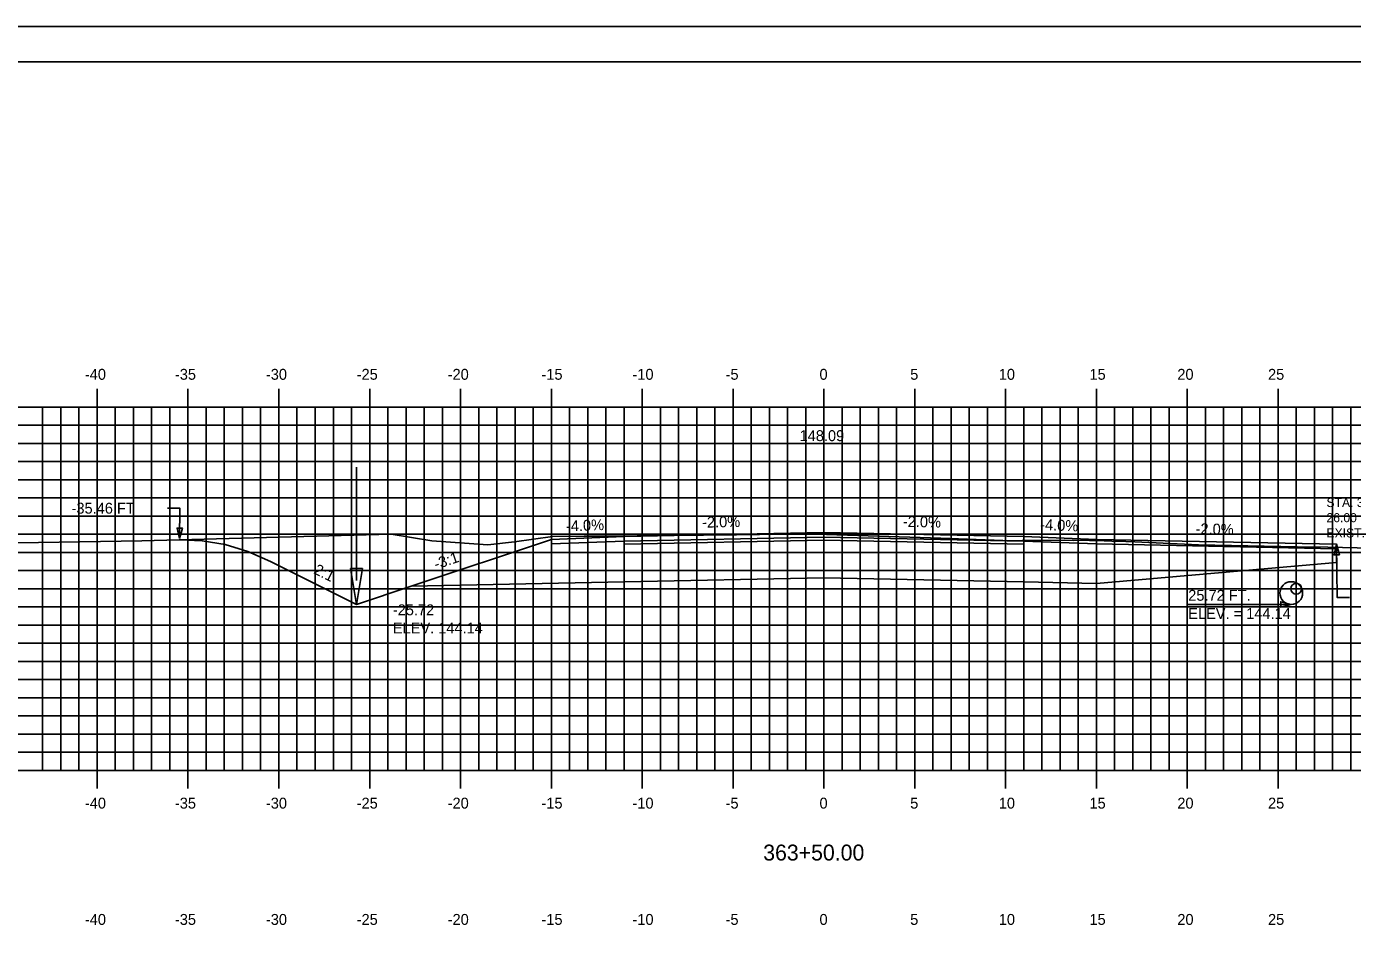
# Model space of a CAD drawing. Extents: x 1146968 to 1147138, y 608981 to 609091.
# Drawn here: x 1147007.3 to 1147080.3, y 609041.6 to 609091.3 of the extents above; entities that cross this region are included whole.
import ezdxf

# ---------------------------------------------------------------- set-up
doc = ezdxf.new("R2010")
doc.units = 0
for name, color, linetype in [('ANNOTATION', 7, 'Continuous'), ('BORDER', 7, 'Continuous'), ('D_Drainage_Culvert', 7, 'Continuous'), ('D_Drainage_Ditch_Line', 7, 'Continuous'), ('D_Roadway_Centerline', 7, 'Continuous'), ('D_Roadway_Centerline_Text', 7, 'Continuous'), ('D_Roadway_Edge_Shoulder', 7, 'Continuous'), ('D_Roadway_Edge_TW', 7, 'Continuous'), ('D_Roadway_Pavement', 7, 'Continuous'), ('D_Roadway_SlopeLines', 7, 'Continuous'), ('D_Roadway_SubGrade', 7, 'Continuous'), ('D_Text_Monospaced', 7, 'Continuous'), ('D_Text_Standard', 7, 'Continuous'), ('H_V ANNOTATION', 7, 'Continuous'), ('MAJOR', 7, 'Continuous'), ('MINOR', 7, 'Continuous'), ('PLOT BOUNDARY', 7, 'Continuous'), ('S_Drainage_Invert', 7, 'Continuous'), ('S_Roadway_Centerline', 7, 'Continuous')]:
    doc.layers.add(name, color=color, linetype=linetype)

msp = doc.modelspace()

# ---------------------------------------------------------------- linework, layer by layer
msp.add_lwpolyline([(1147015.722, 609063.022), (1147016.972, 609062.975), (1147018.222, 609062.762), (1147019.472, 609062.384), (1147020.722, 609061.842), (1147025.46, 609059.473), (1147028.46, 609060.473), (1147036.183, 609063.047), (1147036.184, 609063.047), (1147040.184, 609063.207), (1147051.184, 609063.427), (1147062.184, 609063.207), (1147066.184, 609063.047), (1147079.407, 609062.783)])
at = {"layer": 'BORDER'}
msp.add_lwpolyline([(1146976.185, 608984.335), (1147136.185, 608984.335), (1147136.185, 609089.335), (1146976.185, 609089.335)], close=True, dxfattribs=at)
at = {"layer": 'D_Drainage_Culvert'}
msp.add_circle((1147076.908, 609060.098), 0.625, dxfattribs=at)
at = {"layer": 'D_Drainage_Ditch_Line'}
msp.add_line((1147025.46, 609060.785), (1147025.46, 609067.028), dxfattribs=at)
msp.add_lwpolyline([(1147025.132, 609061.441), (1147025.788, 609061.441), (1147025.46, 609059.473)], close=True, dxfattribs=at)
at = {"layer": 'D_Roadway_Edge_Shoulder'}
for points in [[(1147040.184, 609063.207), (1147036.184, 609063.047), (1147036.184, 609062.797), (1147040.184, 609062.957)], [(1147062.184, 609063.207), (1147066.184, 609063.047), (1147066.184, 609062.797), (1147062.184, 609062.957)], [(1147066.184, 609063.047), (1147079.407, 609062.783), (1147079.407, 609062.533), (1147066.184, 609062.797)]]:
    msp.add_lwpolyline(points, close=True, dxfattribs=at)
at = {"layer": 'D_Roadway_Edge_TW'}
msp.add_lwpolyline([(1147040.184, 609062.957), (1147040.184, 609063.207), (1147051.184, 609063.427), (1147062.184, 609063.207), (1147062.184, 609062.957), (1147051.184, 609063.177)], close=True, dxfattribs=at)
at = {"layer": 'D_Roadway_Pavement'}
msp.add_lwpolyline([(1147040.184, 609062.79), (1147040.184, 609062.957), (1147051.184, 609063.177), (1147062.184, 609062.957), (1147062.184, 609062.79), (1147051.184, 609063.01)], close=True, dxfattribs=at)
at = {"layer": 'D_Roadway_SlopeLines'}
for points in [[(1147025.46, 609059.473), (1147020.722, 609061.842), (1147019.472, 609062.384), (1147018.222, 609062.762), (1147016.972, 609062.975), (1147015.722, 609063.022)], [(1147028.46, 609060.473), (1147025.46, 609059.473)]]:
    msp.add_lwpolyline(points, dxfattribs=at)
at = {"layer": 'D_Roadway_SubGrade'}
for points in [[(1147040.184, 609062.79), (1147040.184, 609062.957), (1147036.184, 609062.797), (1147036.184, 609063.047), (1147036.183, 609063.047), (1147028.46, 609060.473), (1147040.184, 609060.707)], [(1147040.184, 609060.707), (1147040.184, 609062.79), (1147051.184, 609063.01), (1147062.184, 609062.79), (1147062.184, 609060.707), (1147051.184, 609060.927)], [(1147079.407, 609061.783), (1147079.407, 609062.783), (1147066.184, 609063.047), (1147066.184, 609062.797), (1147062.184, 609062.957), (1147062.184, 609062.79), (1147062.184, 609060.707), (1147066.184, 609060.627)]]:
    msp.add_lwpolyline(points, close=True, dxfattribs=at)
at = {"layer": 'D_Text_Standard'}
msp.add_line((1147071.239, 609059.473), (1147075.675, 609059.473), dxfattribs=at)
for points in [[(1147015.722, 609063.092), (1147015.74, 609064.766), (1147015.06, 609064.766)], [(1147079.407, 609062.783), (1147079.435, 609059.861), (1147080.115, 609059.861)], [(1147076.908, 609059.473), (1147076.355, 609059.473), (1147075.675, 609059.473)]]:
    msp.add_lwpolyline(points, dxfattribs=at)
for points in [[(1147015.722, 609063.092), (1147015.582, 609063.675), (1147015.873, 609063.672)], [(1147079.407, 609062.783), (1147079.558, 609062.202), (1147079.267, 609062.199)], [(1147076.908, 609059.473), (1147076.326, 609059.327), (1147076.326, 609059.618)]]:
    msp.add_lwpolyline(points, close=True, dxfattribs=at)
at = {"layer": 'MAJOR'}
for p, q in [((1147011.184, 609071.337), (1147011.184, 609070.335)), ((1147016.184, 609071.337), (1147016.184, 609070.335)), ((1147021.184, 609071.337), (1147021.184, 609070.335)), ((1147026.184, 609071.337), (1147026.184, 609070.335)), ((1147031.184, 609071.337), (1147031.184, 609070.335)), ((1147036.184, 609071.337), (1147036.184, 609070.335)), ((1147041.184, 609071.337), (1147041.184, 609070.335)), ((1147046.184, 609071.337), (1147046.184, 609070.335)), ((1147051.184, 609071.337), (1147051.184, 609070.335)), ((1147056.184, 609071.337), (1147056.184, 609070.335)), ((1147061.184, 609071.337), (1147061.184, 609070.335)), ((1147066.184, 609071.337), (1147066.184, 609070.335)), ((1147071.184, 609071.337), (1147071.184, 609070.335)), ((1147076.184, 609071.337), (1147076.184, 609070.335)), ((1146981.184, 609070.335), (1147121.184, 609070.335)), ((1146981.184, 609070.335), (1147121.184, 609070.335)), ((1147011.184, 609050.335), (1147011.184, 609070.335)), ((1147016.184, 609050.335), (1147016.184, 609070.335)), ((1147021.184, 609050.335), (1147021.184, 609070.335)), ((1147026.184, 609050.335), (1147026.184, 609070.335)), ((1147031.184, 609050.335), (1147031.184, 609070.335)), ((1147036.184, 609050.335), (1147036.184, 609070.335)), ((1147041.184, 609050.335), (1147041.184, 609070.335)), ((1147046.184, 609050.335), (1147046.184, 609070.335)), ((1147051.184, 609050.335), (1147051.184, 609070.335)), ((1147056.184, 609050.335), (1147056.184, 609070.335)), ((1147061.184, 609050.335), (1147061.184, 609070.335)), ((1147066.184, 609050.335), (1147066.184, 609070.335)), ((1147071.184, 609050.335), (1147071.184, 609070.335)), ((1147076.184, 609050.335), (1147076.184, 609070.335)), ((1146981.184, 609065.335), (1147121.184, 609065.335)), ((1146981.184, 609060.335), (1147121.184, 609060.335)), ((1146981.184, 609055.335), (1147121.184, 609055.335)), ((1146981.184, 609050.335), (1147121.184, 609050.335)), ((1146981.184, 609050.335), (1147121.184, 609050.335)), ((1147011.184, 609049.333), (1147011.184, 609050.335)), ((1147016.184, 609049.333), (1147016.184, 609050.335)), ((1147021.184, 609049.333), (1147021.184, 609050.335)), ((1147026.184, 609049.333), (1147026.184, 609050.335)), ((1147031.184, 609049.333), (1147031.184, 609050.335)), ((1147036.184, 609049.333), (1147036.184, 609050.335)), ((1147041.184, 609049.333), (1147041.184, 609050.335)), ((1147046.184, 609049.333), (1147046.184, 609050.335)), ((1147051.184, 609049.333), (1147051.184, 609050.335)), ((1147056.184, 609049.333), (1147056.184, 609050.335)), ((1147061.184, 609049.333), (1147061.184, 609050.335)), ((1147066.184, 609049.333), (1147066.184, 609050.335)), ((1147071.184, 609049.333), (1147071.184, 609050.335)), ((1147076.184, 609049.333), (1147076.184, 609050.335))]:
    msp.add_line(p, q, dxfattribs=at)
at = {"layer": 'MINOR'}
for p, q in [((1147008.184, 609050.335), (1147008.184, 609070.335)), ((1147009.184, 609050.335), (1147009.184, 609070.335)), ((1147010.184, 609050.335), (1147010.184, 609070.335)), ((1147012.184, 609050.335), (1147012.184, 609070.335)), ((1147013.184, 609050.335), (1147013.184, 609070.335)), ((1147014.184, 609050.335), (1147014.184, 609070.335)), ((1147015.184, 609050.335), (1147015.184, 609070.335)), ((1147017.184, 609050.335), (1147017.184, 609070.335)), ((1147018.184, 609050.335), (1147018.184, 609070.335)), ((1147019.184, 609050.335), (1147019.184, 609070.335)), ((1147020.184, 609050.335), (1147020.184, 609070.335)), ((1147022.184, 609050.335), (1147022.184, 609070.335)), ((1147023.184, 609050.335), (1147023.184, 609070.335)), ((1147024.184, 609050.335), (1147024.184, 609070.335)), ((1147025.184, 609050.335), (1147025.184, 609070.335)), ((1147027.184, 609050.335), (1147027.184, 609070.335)), ((1147028.184, 609050.335), (1147028.184, 609070.335)), ((1147029.184, 609050.335), (1147029.184, 609070.335)), ((1147030.184, 609050.335), (1147030.184, 609070.335)), ((1147032.184, 609050.335), (1147032.184, 609070.335)), ((1147033.184, 609050.335), (1147033.184, 609070.335)), ((1147034.184, 609050.335), (1147034.184, 609070.335)), ((1147035.184, 609050.335), (1147035.184, 609070.335)), ((1147037.184, 609050.335), (1147037.184, 609070.335)), ((1147038.184, 609050.335), (1147038.184, 609070.335)), ((1147039.184, 609050.335), (1147039.184, 609070.335)), ((1147040.184, 609050.335), (1147040.184, 609070.335)), ((1147042.184, 609050.335), (1147042.184, 609070.335)), ((1147043.184, 609050.335), (1147043.184, 609070.335)), ((1147044.184, 609050.335), (1147044.184, 609070.335)), ((1147045.184, 609050.335), (1147045.184, 609070.335)), ((1147047.184, 609050.335), (1147047.184, 609070.335)), ((1147048.184, 609050.335), (1147048.184, 609070.335)), ((1147049.184, 609050.335), (1147049.184, 609070.335)), ((1147050.184, 609050.335), (1147050.184, 609070.335)), ((1147052.184, 609050.335), (1147052.184, 609070.335)), ((1147053.184, 609050.335), (1147053.184, 609070.335)), ((1147054.184, 609050.335), (1147054.184, 609070.335)), ((1147055.184, 609050.335), (1147055.184, 609070.335)), ((1147057.184, 609050.335), (1147057.184, 609070.335)), ((1147058.184, 609050.335), (1147058.184, 609070.335)), ((1147059.184, 609050.335), (1147059.184, 609070.335)), ((1147060.184, 609050.335), (1147060.184, 609070.335)), ((1147062.184, 609050.335), (1147062.184, 609070.335)), ((1147063.184, 609050.335), (1147063.184, 609070.335)), ((1147064.184, 609050.335), (1147064.184, 609070.335)), ((1147065.184, 609050.335), (1147065.184, 609070.335)), ((1147067.184, 609050.335), (1147067.184, 609070.335)), ((1147068.184, 609050.335), (1147068.184, 609070.335)), ((1147069.184, 609050.335), (1147069.184, 609070.335)), ((1147070.184, 609050.335), (1147070.184, 609070.335)), ((1147072.184, 609050.335), (1147072.184, 609070.335)), ((1147073.184, 609050.335), (1147073.184, 609070.335)), ((1147074.184, 609050.335), (1147074.184, 609070.335)), ((1147075.184, 609050.335), (1147075.184, 609070.335)), ((1147077.184, 609050.335), (1147077.184, 609070.335)), ((1147078.184, 609050.335), (1147078.184, 609070.335)), ((1147079.184, 609050.335), (1147079.184, 609070.335)), ((1147080.184, 609050.335), (1147080.184, 609070.335)), ((1146981.184, 609069.335), (1147121.184, 609069.335)), ((1146981.184, 609068.335), (1147121.184, 609068.335)), ((1146981.184, 609067.335), (1147121.184, 609067.335)), ((1146981.184, 609066.335), (1147121.184, 609066.335)), ((1146981.184, 609064.335), (1147121.184, 609064.335)), ((1146981.184, 609063.335), (1147121.184, 609063.335)), ((1146981.184, 609062.335), (1147121.184, 609062.335)), ((1146981.184, 609061.335), (1147121.184, 609061.335)), ((1146981.184, 609059.335), (1147121.184, 609059.335)), ((1146981.184, 609058.335), (1147121.184, 609058.335)), ((1146981.184, 609057.335), (1147121.184, 609057.335)), ((1146981.184, 609056.335), (1147121.184, 609056.335)), ((1146981.184, 609054.335), (1147121.184, 609054.335)), ((1146981.184, 609053.335), (1147121.184, 609053.335)), ((1146981.184, 609052.335), (1147121.184, 609052.335)), ((1146981.184, 609051.335), (1147121.184, 609051.335))]:
    msp.add_line(p, q, dxfattribs=at)
at = {"layer": 'PLOT BOUNDARY'}
msp.add_lwpolyline([(1146968.091, 608981.276), (1147138.091, 608981.276), (1147138.091, 609091.276), (1146968.091, 609091.276)], close=True, dxfattribs=at)
at = {"layer": 'S_Drainage_Invert'}
msp.add_circle((1147077.18, 609060.332), 0.3, dxfattribs=at)
at = {"layer": 'S_Roadway_Centerline'}
msp.add_lwpolyline([(1146996.582, 609062.7), (1147013.649, 609062.965), (1147027.368, 609063.344), (1147029.607, 609062.965), (1147032.685, 609062.75), (1147034.164, 609062.912), (1147036.249, 609063.205), (1147037.989, 609063.226), (1147039.093, 609063.226), (1147046.383, 609063.306), (1147050.193, 609063.359), (1147057.625, 609063.125), (1147061.53, 609062.963), (1147062.094, 609062.981), (1147064.419, 609063), (1147064.92, 609062.997), (1147065.221, 609063.007), (1147065.807, 609062.995), (1147066.165, 609062.985), (1147067.033, 609062.961), (1147067.808, 609062.933), (1147068.3, 609062.914), (1147071.805, 609062.751), (1147077.234, 609062.634), (1147078.913, 609062.615), (1147084.574, 609062.494)], dxfattribs=at)

# ---------------------------------------------------------------- texts
at = {"layer": 'ANNOTATION'}
for s, rotation, p in [('-2.0%', 1.14576, (1147044.487, 609063.693)), ('-2.0%', 358.85424, (1147055.527, 609063.74)), ('-4.0%', 2.29061, (1147037, 609063.481)), ('-4.0%', 357.70939, (1147063.08, 609063.572)), ('-2.0%', 358.85424, (1147071.639, 609063.338)), ('-3:1', 18.43482, (1147029.839, 609061.386)), ('2:1', 333.43495, (1147023.058, 609061.192))]:
    msp.add_text(s, height=0.6, rotation=rotation, dxfattribs=at).set_placement(p)
at = {"layer": 'D_Roadway_Centerline'}
for s, p in [('C', (1147051.179, 609063.427)), ('L', (1147051.184, 609063.42))]:
    msp.add_text(s, height=0.0146, dxfattribs=at).set_placement(p)
at = {"layer": 'D_Roadway_Centerline_Text'}
msp.add_text('148.09', height=0.6, dxfattribs=at).set_placement((1147049.847, 609068.459))
at = {"layer": 'D_Text_Monospaced'}
for s, height, p in [('STA. 363+63.25', 0.49998, (1147078.847, 609064.83)), ('26.00 RT.', 0.5, (1147078.847, 609063.996)), ('EXIST. ', 0.5, (1147078.847, 609063.156))]:
    msp.add_text(s, height=height, dxfattribs=at).set_placement(p)
at = {"layer": 'D_Text_Standard'}
for s, p in [('-35.46 FT', (1147009.777, 609064.466)), ('25.72 FT.', (1147071.239, 609059.673)), ('-25.72', (1147027.46, 609058.873)), ('ELEV. = 144.14', (1147071.239, 609058.673)), ('ELEV. 144.14', (1147027.46, 609057.871))]:
    msp.add_text(s, height=0.6, dxfattribs=at).set_placement(p)
at = {"layer": 'H_V ANNOTATION'}
for s, height, p in [('-40', 0.6, (1147010.51, 609071.835)), ('-35', 0.6, (1147015.465, 609071.835)), ('-30', 0.6, (1147020.473, 609071.835)), ('-25', 0.6, (1147025.47, 609071.835)), ('-20', 0.6, (1147030.478, 609071.835)), ('-15', 0.6, (1147035.641, 609071.835)), ('-10', 0.6, (1147040.649, 609071.835)), ('-5', 0.6, (1147045.775, 609071.835)), ('0', 0.6, (1147050.943, 609071.835)), ('5', 0.6, (1147055.935, 609071.835)), ('10', 0.6, (1147060.81, 609071.835)), ('15', 0.6, (1147065.802, 609071.835)), ('20', 0.6, (1147070.638, 609071.835)), ('25', 0.6, (1147075.63, 609071.835)), ('-40', 0.6, (1147010.51, 609048.235)), ('-35', 0.6, (1147015.465, 609048.235)), ('-30', 0.6, (1147020.473, 609048.235)), ('-25', 0.6, (1147025.47, 609048.235)), ('-20', 0.6, (1147030.478, 609048.235)), ('-15', 0.6, (1147035.641, 609048.235)), ('-10', 0.6, (1147040.649, 609048.235)), ('-5', 0.6, (1147045.775, 609048.235)), ('0', 0.6, (1147050.943, 609048.235)), ('5', 0.6, (1147055.935, 609048.235)), ('10', 0.6, (1147060.81, 609048.235)), ('15', 0.6, (1147065.802, 609048.235)), ('20', 0.6, (1147070.638, 609048.235)), ('25', 0.6, (1147075.63, 609048.235)), ('363+50.00', 0.875, (1147047.845, 609045.378)), ('-40', 0.6, (1147010.51, 609041.835)), ('-35', 0.6, (1147015.465, 609041.835)), ('-30', 0.6, (1147020.473, 609041.835)), ('-25', 0.6, (1147025.47, 609041.835)), ('-20', 0.6, (1147030.478, 609041.835)), ('-15', 0.6, (1147035.641, 609041.835)), ('-10', 0.6, (1147040.649, 609041.835)), ('-5', 0.6, (1147045.775, 609041.835)), ('0', 0.6, (1147050.943, 609041.835)), ('5', 0.6, (1147055.935, 609041.835)), ('10', 0.6, (1147060.81, 609041.835)), ('15', 0.6, (1147065.802, 609041.835)), ('20', 0.6, (1147070.638, 609041.835)), ('25', 0.6, (1147075.63, 609041.835))]:
    msp.add_text(s, height=height, dxfattribs=at).set_placement(p)
at = {"layer": 'S_Roadway_Centerline'}
for s, p in [('L', (1147050.184, 609063.351)), ('C', (1147050.187, 609063.359))]:
    msp.add_text(s, height=0.0146, dxfattribs=at).set_placement(p)

doc.saveas('drawing.dxf')
